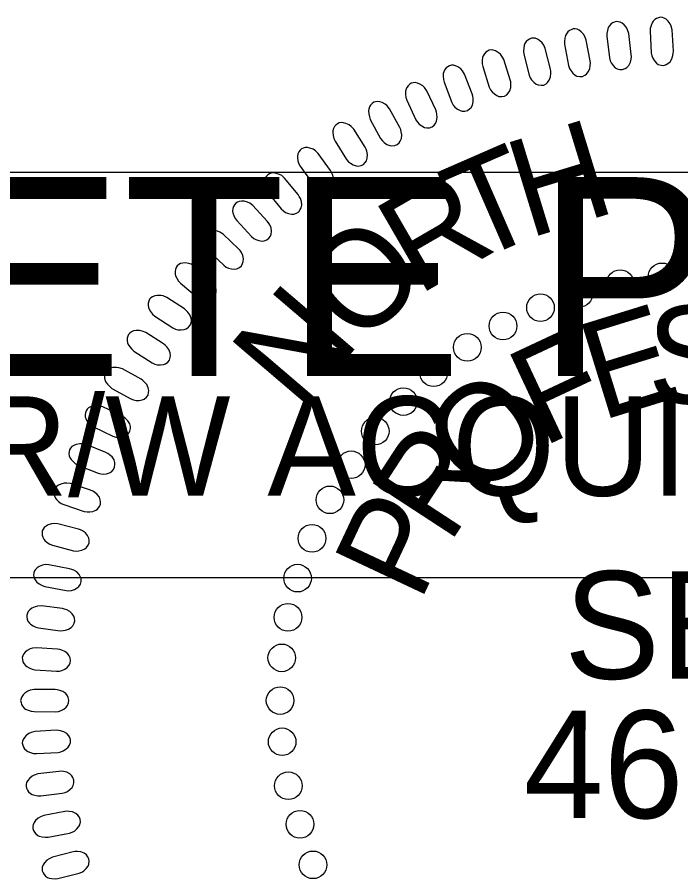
# Model space of a CAD drawing. Extents: x 505569 to 516904, y 436011 to 484484.
# Drawn here: x 507178.88 to 507217.35, y 484085.05 to 484134.99 of the extents above; entities that cross this region are included whole.
import ezdxf

# ---------------------------------------------------------------- set-up
doc = ezdxf.new("R2010")
doc.units = 0
doc.layers.add('Prop VPI Label', color=7, linetype='Continuous')
doc.layers.add('Scratch_Level_5', color=7, linetype='Continuous')

msp = doc.modelspace()

# ---------------------------------------------------------------- linework, layer by layer
at = {"layer": 'Prop VPI Label'}
msp.add_lwpolyline([(507095.597, 484102.505), (507095.597, 484126.005), (507242.597, 484126.005), (507242.597, 484102.505)], close=True, dxfattribs=at)
at = {"layer": 'Scratch_Level_5'}
for points in [[(507216.92, 484133.033), (507216.843, 484134.257), (507216.792, 484134.474), (507216.731, 484134.609), (507216.609, 484134.772), (507216.505, 484134.876), (507216.388, 484134.948), (507216.281, 484134.981), (507216.168, 484134.994), (507216.057, 484134.967), (507215.94, 484134.93), (507215.839, 484134.864), (507215.741, 484134.758), (507215.687, 484134.674), (507215.628, 484134.521), (507215.58, 484134.338), (507215.568, 484134.178), (507215.639, 484132.923), (507215.671, 484132.755), (507215.725, 484132.618), (507215.824, 484132.465), (507215.945, 484132.332), (507216.047, 484132.259), (507216.208, 484132.209), (507216.358, 484132.198), (507216.505, 484132.247), (507216.606, 484132.304), (507216.727, 484132.411), (507216.835, 484132.588), (507216.891, 484132.772), (507216.913, 484132.903)], [(507214.482, 484132.83), (507214.328, 484134.047), (507214.264, 484134.26), (507214.194, 484134.392), (507214.062, 484134.546), (507213.952, 484134.643), (507213.831, 484134.708), (507213.722, 484134.735), (507213.608, 484134.741), (507213.499, 484134.706), (507213.384, 484134.662), (507213.288, 484134.59), (507213.196, 484134.478), (507213.147, 484134.391), (507213.099, 484134.234), (507213.062, 484134.049), (507213.06, 484133.887), (507213.21, 484132.64), (507213.253, 484132.474), (507213.315, 484132.341), (507213.424, 484132.194), (507213.553, 484132.07), (507213.659, 484132.003), (507213.822, 484131.963), (507213.973, 484131.962), (507214.116, 484132.02), (507214.214, 484132.083), (507214.328, 484132.198), (507214.425, 484132.38), (507214.469, 484132.567), (507214.483, 484132.699)], [(507212.1, 484132.462), (507211.871, 484133.666), (507211.793, 484133.875), (507211.716, 484134.003), (507211.574, 484134.149), (507211.458, 484134.238), (507211.333, 484134.296), (507211.223, 484134.315), (507211.109, 484134.314), (507211.002, 484134.273), (507210.891, 484134.221), (507210.799, 484134.143), (507210.714, 484134.025), (507210.671, 484133.936), (507210.633, 484133.776), (507210.608, 484133.589), (507210.615, 484133.428), (507210.843, 484132.192), (507210.897, 484132.03), (507210.967, 484131.901), (507211.085, 484131.761), (507211.221, 484131.645), (507211.332, 484131.585), (507211.497, 484131.555), (507211.647, 484131.564), (507211.787, 484131.631), (507211.881, 484131.699), (507211.987, 484131.821), (507212.073, 484132.01), (507212.105, 484132.199), (507212.11, 484132.332)], [(507209.795, 484131.99), (507209.491, 484133.178), (507209.4, 484133.381), (507209.314, 484133.504), (507209.164, 484133.64), (507209.042, 484133.722), (507208.914, 484133.771), (507208.802, 484133.785), (507208.689, 484133.776), (507208.585, 484133.729), (507208.477, 484133.67), (507208.39, 484133.586), (507208.314, 484133.463), (507208.276, 484133.371), (507208.247, 484133.209), (507208.234, 484133.021), (507208.252, 484132.861), (507208.557, 484131.642), (507208.621, 484131.483), (507208.699, 484131.359), (507208.826, 484131.227), (507208.969, 484131.119), (507209.083, 484131.067), (507209.25, 484131.047), (507209.4, 484131.065), (507209.535, 484131.14), (507209.624, 484131.215), (507209.722, 484131.343), (507209.795, 484131.537), (507209.816, 484131.728), (507209.813, 484131.86)], [(507207.461, 484131.369), (507207.083, 484132.536), (507206.98, 484132.733), (507206.887, 484132.85), (507206.728, 484132.977), (507206.602, 484133.051), (507206.47, 484133.092), (507206.358, 484133.098), (507206.246, 484133.082), (507206.145, 484133.029), (507206.041, 484132.963), (507205.96, 484132.874), (507205.891, 484132.747), (507205.859, 484132.652), (507205.84, 484132.489), (507205.839, 484132.3), (507205.867, 484132.141), (507206.248, 484130.944), (507206.322, 484130.79), (507206.407, 484130.671), (507206.542, 484130.547), (507206.692, 484130.448), (507206.809, 484130.403), (507206.977, 484130.394), (507207.125, 484130.421), (507207.255, 484130.505), (507207.339, 484130.585), (507207.429, 484130.719), (507207.49, 484130.917), (507207.499, 484131.109), (507207.487, 484131.242)], [(507205.261, 484130.553), (507204.809, 484131.694), (507204.694, 484131.884), (507204.594, 484131.995), (507204.427, 484132.111), (507204.297, 484132.177), (507204.163, 484132.21), (507204.051, 484132.209), (507203.94, 484132.186), (507203.843, 484132.126), (507203.742, 484132.054), (507203.667, 484131.96), (507203.606, 484131.829), (507203.58, 484131.733), (507203.572, 484131.569), (507203.583, 484131.38), (507203.621, 484131.224), (507204.076, 484130.052), (507204.159, 484129.903), (507204.253, 484129.79), (507204.395, 484129.674), (507204.55, 484129.585), (507204.67, 484129.547), (507204.838, 484129.549), (507204.984, 484129.586), (507205.108, 484129.678), (507205.187, 484129.763), (507205.269, 484129.902), (507205.318, 484130.103), (507205.314, 484130.296), (507205.295, 484130.427)], [(507203.143, 484129.62), (507202.621, 484130.73), (507202.494, 484130.912), (507202.387, 484131.017), (507202.214, 484131.123), (507202.079, 484131.18), (507201.944, 484131.205), (507201.832, 484131.197), (507201.722, 484131.167), (507201.629, 484131.101), (507201.534, 484131.023), (507201.464, 484130.925), (507201.412, 484130.79), (507201.392, 484130.692), (507201.395, 484130.528), (507201.417, 484130.34), (507201.464, 484130.186), (507201.993, 484129.047), (507202.085, 484128.902), (507202.185, 484128.795), (507202.334, 484128.689), (507202.495, 484128.61), (507202.617, 484128.579), (507202.784, 484128.592), (507202.928, 484128.637), (507203.046, 484128.737), (507203.12, 484128.827), (507203.192, 484128.971), (507203.229, 484129.175), (507203.213, 484129.366), (507203.185, 484129.497)], [(507201.06, 484128.606), (507200.469, 484129.681), (507200.331, 484129.856), (507200.218, 484129.953), (507200.038, 484130.048), (507199.9, 484130.097), (507199.764, 484130.113), (507199.653, 484130.097), (507199.545, 484130.061), (507199.456, 484129.99), (507199.366, 484129.906), (507199.303, 484129.803), (507199.259, 484129.665), (507199.245, 484129.566), (507199.258, 484129.403), (507199.292, 484129.216), (507199.349, 484129.066), (507199.948, 484127.961), (507200.049, 484127.823), (507200.156, 484127.723), (507200.311, 484127.626), (507200.477, 484127.557), (507200.6, 484127.534), (507200.767, 484127.557), (507200.907, 484127.612), (507201.019, 484127.719), (507201.087, 484127.813), (507201.15, 484127.961), (507201.173, 484128.168), (507201.146, 484128.357), (507201.109, 484128.485)], [(507199.043, 484127.464), (507198.386, 484128.5), (507198.237, 484128.666), (507198.118, 484128.755), (507197.933, 484128.839), (507197.792, 484128.879), (507197.655, 484128.886), (507197.544, 484128.864), (507197.439, 484128.821), (507197.355, 484128.744), (507197.27, 484128.655), (507197.214, 484128.548), (507197.179, 484128.408), (507197.171, 484128.308), (507197.194, 484128.146), (507197.24, 484127.963), (507197.306, 484127.815), (507197.973, 484126.75), (507198.083, 484126.619), (507198.196, 484126.525), (507198.357, 484126.439), (507198.526, 484126.381), (507198.651, 484126.365), (507198.816, 484126.399), (507198.952, 484126.462), (507199.058, 484126.576), (507199.119, 484126.674), (507199.173, 484126.826), (507199.183, 484127.034), (507199.144, 484127.222), (507199.1, 484127.346)], [(507197.042, 484126.109), (507196.321, 484127.102), (507196.162, 484127.258), (507196.038, 484127.34), (507195.847, 484127.412), (507195.704, 484127.443), (507195.567, 484127.442), (507195.458, 484127.413), (507195.356, 484127.363), (507195.277, 484127.281), (507195.198, 484127.187), (507195.149, 484127.077), (507195.122, 484126.934), (507195.121, 484126.835), (507195.155, 484126.674), (507195.211, 484126.493), (507195.287, 484126.351), (507196.019, 484125.33), (507196.137, 484125.206), (507196.255, 484125.119), (507196.421, 484125.043), (507196.594, 484124.996), (507196.72, 484124.988), (507196.882, 484125.032), (507197.015, 484125.104), (507197.112, 484125.224), (507197.167, 484125.325), (507197.212, 484125.481), (507197.209, 484125.689), (507197.158, 484125.873), (507197.106, 484125.996)], [(507195.162, 484124.721), (507194.38, 484125.666), (507194.212, 484125.811), (507194.082, 484125.886), (507193.888, 484125.945), (507193.743, 484125.968), (507193.606, 484125.958), (507193.5, 484125.921), (507193.401, 484125.865), (507193.327, 484125.778), (507193.254, 484125.679), (507193.211, 484125.567), (507193.194, 484125.423), (507193.199, 484125.323), (507193.242, 484125.165), (507193.31, 484124.988), (507193.395, 484124.851), (507194.189, 484123.878), (507194.315, 484123.762), (507194.439, 484123.683), (507194.609, 484123.617), (507194.785, 484123.581), (507194.911, 484123.581), (507195.07, 484123.635), (507195.198, 484123.715), (507195.287, 484123.841), (507195.336, 484123.946), (507195.371, 484124.104), (507195.354, 484124.31), (507195.292, 484124.492), (507195.232, 484124.611)], [(507193.374, 484123.181), (507192.535, 484124.076), (507192.357, 484124.211), (507192.223, 484124.277), (507192.025, 484124.324), (507191.88, 484124.337), (507191.744, 484124.319), (507191.64, 484124.276), (507191.544, 484124.214), (507191.476, 484124.122), (507191.409, 484124.018), (507191.374, 484123.904), (507191.366, 484123.759), (507191.377, 484123.66), (507191.43, 484123.505), (507191.51, 484123.333), (507191.602, 484123.202), (507192.457, 484122.28), (507192.589, 484122.172), (507192.717, 484122.101), (507192.892, 484122.046), (507193.07, 484122.02), (507193.195, 484122.028), (507193.35, 484122.092), (507193.473, 484122.181), (507193.554, 484122.312), (507193.597, 484122.42), (507193.622, 484122.579), (507193.593, 484122.785), (507193.518, 484122.962), (507193.452, 484123.077)], [(507191.712, 484121.572), (507190.818, 484122.412), (507190.632, 484122.535), (507190.495, 484122.593), (507190.294, 484122.627), (507190.148, 484122.632), (507190.013, 484122.604), (507189.912, 484122.555), (507189.821, 484122.487), (507189.759, 484122.392), (507189.699, 484122.284), (507189.67, 484122.167), (507189.671, 484122.023), (507189.689, 484121.924), (507189.751, 484121.772), (507189.841, 484121.606), (507189.942, 484121.48), (507190.853, 484120.615), (507190.992, 484120.515), (507191.124, 484120.452), (507191.302, 484120.408), (507191.48, 484120.394), (507191.605, 484120.41), (507191.757, 484120.484), (507191.873, 484120.579), (507191.946, 484120.715), (507191.982, 484120.826), (507191.996, 484120.987), (507191.955, 484121.19), (507191.87, 484121.362), (507191.796, 484121.472)], [(507190.098, 484119.785), (507189.154, 484120.568), (507188.96, 484120.678), (507188.82, 484120.727), (507188.617, 484120.749), (507188.471, 484120.744), (507188.339, 484120.709), (507188.241, 484120.654), (507188.154, 484120.58), (507188.098, 484120.481), (507188.045, 484120.369), (507188.024, 484120.251), (507188.034, 484120.107), (507188.057, 484120.01), (507188.13, 484119.863), (507188.23, 484119.701), (507188.338, 484119.583), (507189.301, 484118.776), (507189.446, 484118.685), (507189.583, 484118.631), (507189.763, 484118.598), (507189.941, 484118.595), (507190.065, 484118.62), (507190.211, 484118.702), (507190.322, 484118.804), (507190.387, 484118.945), (507190.415, 484119.057), (507190.419, 484119.219), (507190.365, 484119.419), (507190.27, 484119.585), (507190.188, 484119.691)], [(507188.574, 484118.083), (507187.544, 484118.749), (507187.339, 484118.836), (507187.193, 484118.868), (507186.99, 484118.866), (507186.845, 484118.844), (507186.718, 484118.793), (507186.628, 484118.727), (507186.55, 484118.643), (507186.505, 484118.539), (507186.466, 484118.422), (507186.459, 484118.302), (507186.486, 484118.16), (507186.52, 484118.066), (507186.61, 484117.928), (507186.728, 484117.78), (507186.85, 484117.675), (507187.901, 484116.987), (507188.056, 484116.914), (507188.197, 484116.876), (507188.38, 484116.864), (507188.558, 484116.883), (507188.678, 484116.922), (507188.813, 484117.021), (507188.911, 484117.135), (507188.959, 484117.283), (507188.974, 484117.397), (507188.959, 484117.558), (507188.882, 484117.75), (507188.767, 484117.905), (507188.674, 484118)], [(507187.359, 484116.06), (507186.324, 484116.718), (507186.119, 484116.804), (507185.973, 484116.835), (507185.769, 484116.831), (507185.625, 484116.808), (507185.497, 484116.756), (507185.408, 484116.689), (507185.33, 484116.605), (507185.287, 484116.499), (507185.249, 484116.383), (507185.243, 484116.262), (507185.271, 484116.121), (507185.306, 484116.027), (507185.397, 484115.89), (507185.516, 484115.743), (507185.639, 484115.639), (507186.696, 484114.959), (507186.851, 484114.887), (507186.993, 484114.85), (507187.175, 484114.84), (507187.353, 484114.86), (507187.473, 484114.899), (507187.607, 484115), (507187.704, 484115.115), (507187.751, 484115.263), (507187.765, 484115.378), (507187.749, 484115.539), (507187.67, 484115.73), (507187.554, 484115.883), (507187.461, 484115.978)], [(507186.056, 484114.011), (507184.981, 484114.603), (507184.771, 484114.675), (507184.623, 484114.697), (507184.421, 484114.681), (507184.277, 484114.648), (507184.154, 484114.589), (507184.069, 484114.516), (507183.997, 484114.428), (507183.961, 484114.32), (507183.929, 484114.2), (507183.931, 484114.08), (507183.968, 484113.94), (507184.009, 484113.849), (507184.107, 484113.718), (507184.236, 484113.579), (507184.365, 484113.482), (507185.462, 484112.871), (507185.621, 484112.808), (507185.765, 484112.781), (507185.949, 484112.782), (507186.125, 484112.813), (507186.242, 484112.86), (507186.37, 484112.968), (507186.459, 484113.09), (507186.496, 484113.24), (507186.503, 484113.355), (507186.477, 484113.515), (507186.386, 484113.701), (507186.262, 484113.847), (507186.162, 484113.936)], [(507184.947, 484111.887), (507183.837, 484112.41), (507183.623, 484112.47), (507183.474, 484112.482), (507183.273, 484112.453), (507183.132, 484112.412), (507183.013, 484112.344), (507182.932, 484112.266), (507182.866, 484112.173), (507182.836, 484112.063), (507182.813, 484111.942), (507182.822, 484111.823), (507182.868, 484111.685), (507182.914, 484111.597), (507183.021, 484111.473), (507183.158, 484111.342), (507183.292, 484111.253), (507184.427, 484110.711), (507184.589, 484110.66), (507184.735, 484110.641), (507184.917, 484110.654), (507185.091, 484110.696), (507185.205, 484110.749), (507185.326, 484110.866), (507185.408, 484110.993), (507185.435, 484111.145), (507185.435, 484111.261), (507185.399, 484111.419), (507185.297, 484111.599), (507185.163, 484111.736), (507185.058, 484111.819)], [(507184.008, 484109.769), (507182.868, 484110.22), (507182.65, 484110.266), (507182.501, 484110.27), (507182.302, 484110.228), (507182.164, 484110.178), (507182.049, 484110.103), (507181.973, 484110.02), (507181.913, 484109.923), (507181.89, 484109.812), (507181.874, 484109.689), (507181.891, 484109.57), (507181.945, 484109.436), (507181.997, 484109.351), (507182.112, 484109.233), (507182.257, 484109.112), (507182.396, 484109.032), (507183.562, 484108.562), (507183.727, 484108.521), (507183.874, 484108.511), (507184.055, 484108.535), (507184.226, 484108.588), (507184.337, 484108.649), (507184.451, 484108.773), (507184.524, 484108.904), (507184.542, 484109.058), (507184.534, 484109.174), (507184.488, 484109.329), (507184.374, 484109.502), (507184.232, 484109.631), (507184.122, 484109.707)], [(507183.132, 484107.579), (507181.965, 484107.958), (507181.745, 484107.99), (507181.596, 484107.985), (507181.4, 484107.931), (507181.265, 484107.872), (507181.155, 484107.79), (507181.085, 484107.703), (507181.032, 484107.602), (507181.016, 484107.489), (507181.007, 484107.366), (507181.032, 484107.249), (507181.094, 484107.118), (507181.152, 484107.036), (507181.273, 484106.926), (507181.425, 484106.814), (507181.57, 484106.743), (507182.763, 484106.347), (507182.931, 484106.316), (507183.078, 484106.316), (507183.257, 484106.352), (507183.424, 484106.415), (507183.531, 484106.483), (507183.636, 484106.613), (507183.701, 484106.749), (507183.709, 484106.904), (507183.694, 484107.019), (507183.639, 484107.171), (507183.515, 484107.337), (507183.364, 484107.456), (507183.25, 484107.525)], [(507182.428, 484105.324), (507181.239, 484105.629), (507181.018, 484105.647), (507180.869, 484105.632), (507180.677, 484105.565), (507180.547, 484105.499), (507180.441, 484105.41), (507180.377, 484105.318), (507180.329, 484105.214), (507180.321, 484105.102), (507180.32, 484104.978), (507180.352, 484104.861), (507180.423, 484104.736), (507180.485, 484104.658), (507180.613, 484104.555), (507180.772, 484104.453), (507180.921, 484104.391), (507182.136, 484104.071), (507182.306, 484104.05), (507182.452, 484104.059), (507182.629, 484104.107), (507182.792, 484104.18), (507182.894, 484104.254), (507182.991, 484104.392), (507183.047, 484104.531), (507183.046, 484104.686), (507183.024, 484104.8), (507182.959, 484104.948), (507182.825, 484105.106), (507182.667, 484105.216), (507182.549, 484105.277)], [(507181.916, 484103.028), (507180.712, 484103.258), (507180.489, 484103.263), (507180.342, 484103.238), (507180.154, 484103.159), (507180.028, 484103.085), (507179.929, 484102.989), (507179.87, 484102.894), (507179.829, 484102.788), (507179.828, 484102.674), (507179.835, 484102.551), (507179.874, 484102.437), (507179.952, 484102.315), (507180.019, 484102.242), (507180.154, 484102.147), (507180.319, 484102.055), (507180.471, 484102.003), (507181.705, 484101.759), (507181.875, 484101.75), (507182.021, 484101.768), (507182.194, 484101.826), (507182.352, 484101.91), (507182.449, 484101.99), (507182.537, 484102.133), (507182.585, 484102.276), (507182.574, 484102.431), (507182.544, 484102.543), (507182.47, 484102.686), (507182.327, 484102.836), (507182.162, 484102.936), (507182.041, 484102.989)], [(507181.496, 484100.713), (507180.279, 484100.867), (507180.057, 484100.858), (507179.911, 484100.824), (507179.729, 484100.734), (507179.608, 484100.652), (507179.515, 484100.55), (507179.462, 484100.452), (507179.428, 484100.342), (507179.434, 484100.229), (507179.449, 484100.106), (507179.495, 484099.995), (507179.581, 484099.879), (507179.653, 484099.81), (507179.792, 484099.724), (507179.963, 484099.642), (507180.118, 484099.6), (507181.364, 484099.434), (507181.535, 484099.436), (507181.679, 484099.463), (507181.848, 484099.531), (507182.001, 484099.625), (507182.093, 484099.712), (507182.172, 484099.86), (507182.211, 484100.006), (507182.189, 484100.159), (507182.153, 484100.269), (507182.07, 484100.408), (507181.917, 484100.547), (507181.747, 484100.637), (507181.623, 484100.682)], [(507181.21, 484098.37), (507179.985, 484098.447), (507179.764, 484098.424), (507179.621, 484098.38), (507179.445, 484098.279), (507179.329, 484098.189), (507179.242, 484098.082), (507179.196, 484097.98), (507179.169, 484097.87), (507179.182, 484097.757), (507179.205, 484097.635), (507179.257, 484097.527), (507179.35, 484097.416), (507179.426, 484097.352), (507179.571, 484097.275), (507179.746, 484097.204), (507179.904, 484097.171), (507181.158, 484097.084), (507181.329, 484097.096), (507181.471, 484097.132), (507181.636, 484097.212), (507181.782, 484097.315), (507181.868, 484097.407), (507181.937, 484097.56), (507181.967, 484097.708), (507181.936, 484097.859), (507181.893, 484097.967), (507181.802, 484098.1), (507181.64, 484098.23), (507181.465, 484098.309), (507181.338, 484098.346)], [(507181.08, 484096.019), (507179.853, 484096.019), (507179.634, 484095.981), (507179.493, 484095.93), (507179.324, 484095.818), (507179.214, 484095.72), (507179.135, 484095.608), (507179.095, 484095.504), (507179.075, 484095.391), (507179.095, 484095.28), (507179.124, 484095.16), (507179.184, 484095.055), (507179.284, 484094.95), (507179.364, 484094.891), (507179.513, 484094.823), (507179.693, 484094.763), (507179.852, 484094.741), (507181.109, 484094.733), (507181.278, 484094.755), (507181.418, 484094.8), (507181.577, 484094.89), (507181.717, 484095.002), (507181.797, 484095.099), (507181.857, 484095.256), (507181.877, 484095.406), (507181.837, 484095.555), (507181.787, 484095.66), (507181.688, 484095.787), (507181.518, 484095.907), (507181.339, 484095.974), (507181.209, 484096.004)], [(507181.132, 484093.661), (507179.907, 484093.585), (507179.691, 484093.534), (507179.555, 484093.473), (507179.392, 484093.35), (507179.288, 484093.246), (507179.216, 484093.129), (507179.183, 484093.023), (507179.171, 484092.909), (507179.198, 484092.799), (507179.235, 484092.681), (507179.3, 484092.58), (507179.407, 484092.482), (507179.49, 484092.428), (507179.644, 484092.37), (507179.827, 484092.321), (507179.987, 484092.309), (507181.242, 484092.38), (507181.41, 484092.413), (507181.546, 484092.467), (507181.7, 484092.566), (507181.832, 484092.687), (507181.906, 484092.788), (507181.956, 484092.949), (507181.966, 484093.099), (507181.917, 484093.246), (507181.861, 484093.348), (507181.753, 484093.468), (507181.577, 484093.577), (507181.393, 484093.633), (507181.262, 484093.655)], [(507181.297, 484091.28), (507180.079, 484091.127), (507179.867, 484091.062), (507179.734, 484090.993), (507179.58, 484090.861), (507179.483, 484090.75), (507179.418, 484090.629), (507179.392, 484090.52), (507179.386, 484090.406), (507179.42, 484090.298), (507179.465, 484090.183), (507179.537, 484090.086), (507179.649, 484089.995), (507179.736, 484089.945), (507179.892, 484089.898), (507180.078, 484089.861), (507180.239, 484089.859), (507181.487, 484090.008), (507181.652, 484090.051), (507181.785, 484090.114), (507181.932, 484090.222), (507182.057, 484090.351), (507182.124, 484090.457), (507182.164, 484090.621), (507182.164, 484090.772), (507182.106, 484090.915), (507182.044, 484091.013), (507181.929, 484091.127), (507181.746, 484091.223), (507181.559, 484091.268), (507181.427, 484091.281)], [(507181.63, 484088.955), (507180.425, 484088.725), (507180.216, 484088.647), (507180.089, 484088.571), (507179.943, 484088.428), (507179.853, 484088.312), (507179.796, 484088.187), (507179.777, 484088.077), (507179.778, 484087.963), (507179.819, 484087.857), (507179.871, 484087.745), (507179.948, 484087.653), (507180.067, 484087.569), (507180.156, 484087.525), (507180.316, 484087.487), (507180.503, 484087.462), (507180.664, 484087.469), (507181.9, 484087.697), (507182.062, 484087.751), (507182.191, 484087.821), (507182.33, 484087.939), (507182.447, 484088.076), (507182.507, 484088.186), (507182.537, 484088.351), (507182.528, 484088.502), (507182.461, 484088.641), (507182.393, 484088.735), (507182.271, 484088.841), (507182.082, 484088.926), (507181.892, 484088.959), (507181.76, 484088.964)], [(507182.11, 484086.613), (507180.921, 484086.309), (507180.718, 484086.218), (507180.595, 484086.133), (507180.459, 484085.982), (507180.377, 484085.861), (507180.328, 484085.732), (507180.315, 484085.621), (507180.324, 484085.507), (507180.371, 484085.404), (507180.429, 484085.296), (507180.513, 484085.209), (507180.636, 484085.132), (507180.728, 484085.094), (507180.89, 484085.066), (507181.079, 484085.053), (507181.239, 484085.071), (507182.458, 484085.375), (507182.617, 484085.439), (507182.74, 484085.518), (507182.873, 484085.644), (507182.98, 484085.787), (507183.033, 484085.901), (507183.052, 484086.068), (507183.034, 484086.218), (507182.959, 484086.353), (507182.884, 484086.442), (507182.756, 484086.541), (507182.562, 484086.614), (507182.371, 484086.635), (507182.239, 484086.631)]]:
    msp.add_lwpolyline(points, close=True, dxfattribs=at)
for centre in [(507216.263, 484119.946), (507213.835, 484119.548), (507211.446, 484118.992), (507209.216, 484118.156), (507207.041, 484117.095), (507204.971, 484115.861), (507203.019, 484114.387), (507201.267, 484112.715), (507199.634, 484111.002), (507198.24, 484109.051), (507197.005, 484107.019), (507195.969, 484104.789), (507195.132, 484102.479), (507194.574, 484100.208), (507194.215, 484097.858), (507194.119, 484095.383), (507194.237, 484092.993), (507194.595, 484090.443), (507195.271, 484088.212), (507196.027, 484085.861)]:
    msp.add_circle(centre, 0.801, dxfattribs=at)

# ---------------------------------------------------------------- texts
at = {"layer": 'Prop VPI Label'}
for s, height, p in [('INCOMPLETE PLANS', 11.52, (507104.547, 484114.205)), ('DO NOT USE FOR R/W ACQUISITION', 5.76, (507107.797, 484107.255))]:
    msp.add_text(s, height=height, dxfattribs=at).set_placement(p)
at = {"layer": 'Scratch_Level_5'}
for s, height, rotation, p in [('H', 5.669, 17.0557, (507208.505, 484122.153)), ('T', 5.669, 23.5451, (507205.326, 484120.743)), ('R', 5.669, 30.0345, (507202.105, 484118.824)), ('O', 5.669, 43.0132, (507198.63, 484115.796)), ('N', 5.669, 49.5025, (507195.283, 484112.041)), ('E', 5.669, 17.1686, (507212.701, 484111.584)), ('S', 5.669, 1.289, (507215.468, 484112.543)), ('F', 5.669, 25.1084, (507209.311, 484110.045)), ('O', 5.669, 40.988, (507205.614, 484106.907)), ('R', 5.669, 56.8676, (507203.9, 484104.36)), ('P', 5.669, 64.8074, (507202.214, 484100.998)), ('SEAL', 6.2363, 359.9814, (507210.585, 484096.649)), ('46155', 6.2363, 359.9814, (507208.236, 484088.571))]:
    msp.add_text(s, height=height, rotation=rotation, dxfattribs=at).set_placement(p)

doc.saveas('drawing.dxf')
